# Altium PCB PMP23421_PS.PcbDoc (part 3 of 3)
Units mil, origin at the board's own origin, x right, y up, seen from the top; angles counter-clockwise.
Board outline 1978.53 x 2528.22 mil, 6 copper layers (Top Layer, Signal Layer 1, Signal Layer 2, Signal Layer 3, Signal Layer 4, Bottom Layer), stack 61.3 mil thick; 156 components, 45 nets, 410 pads, 635 vias.
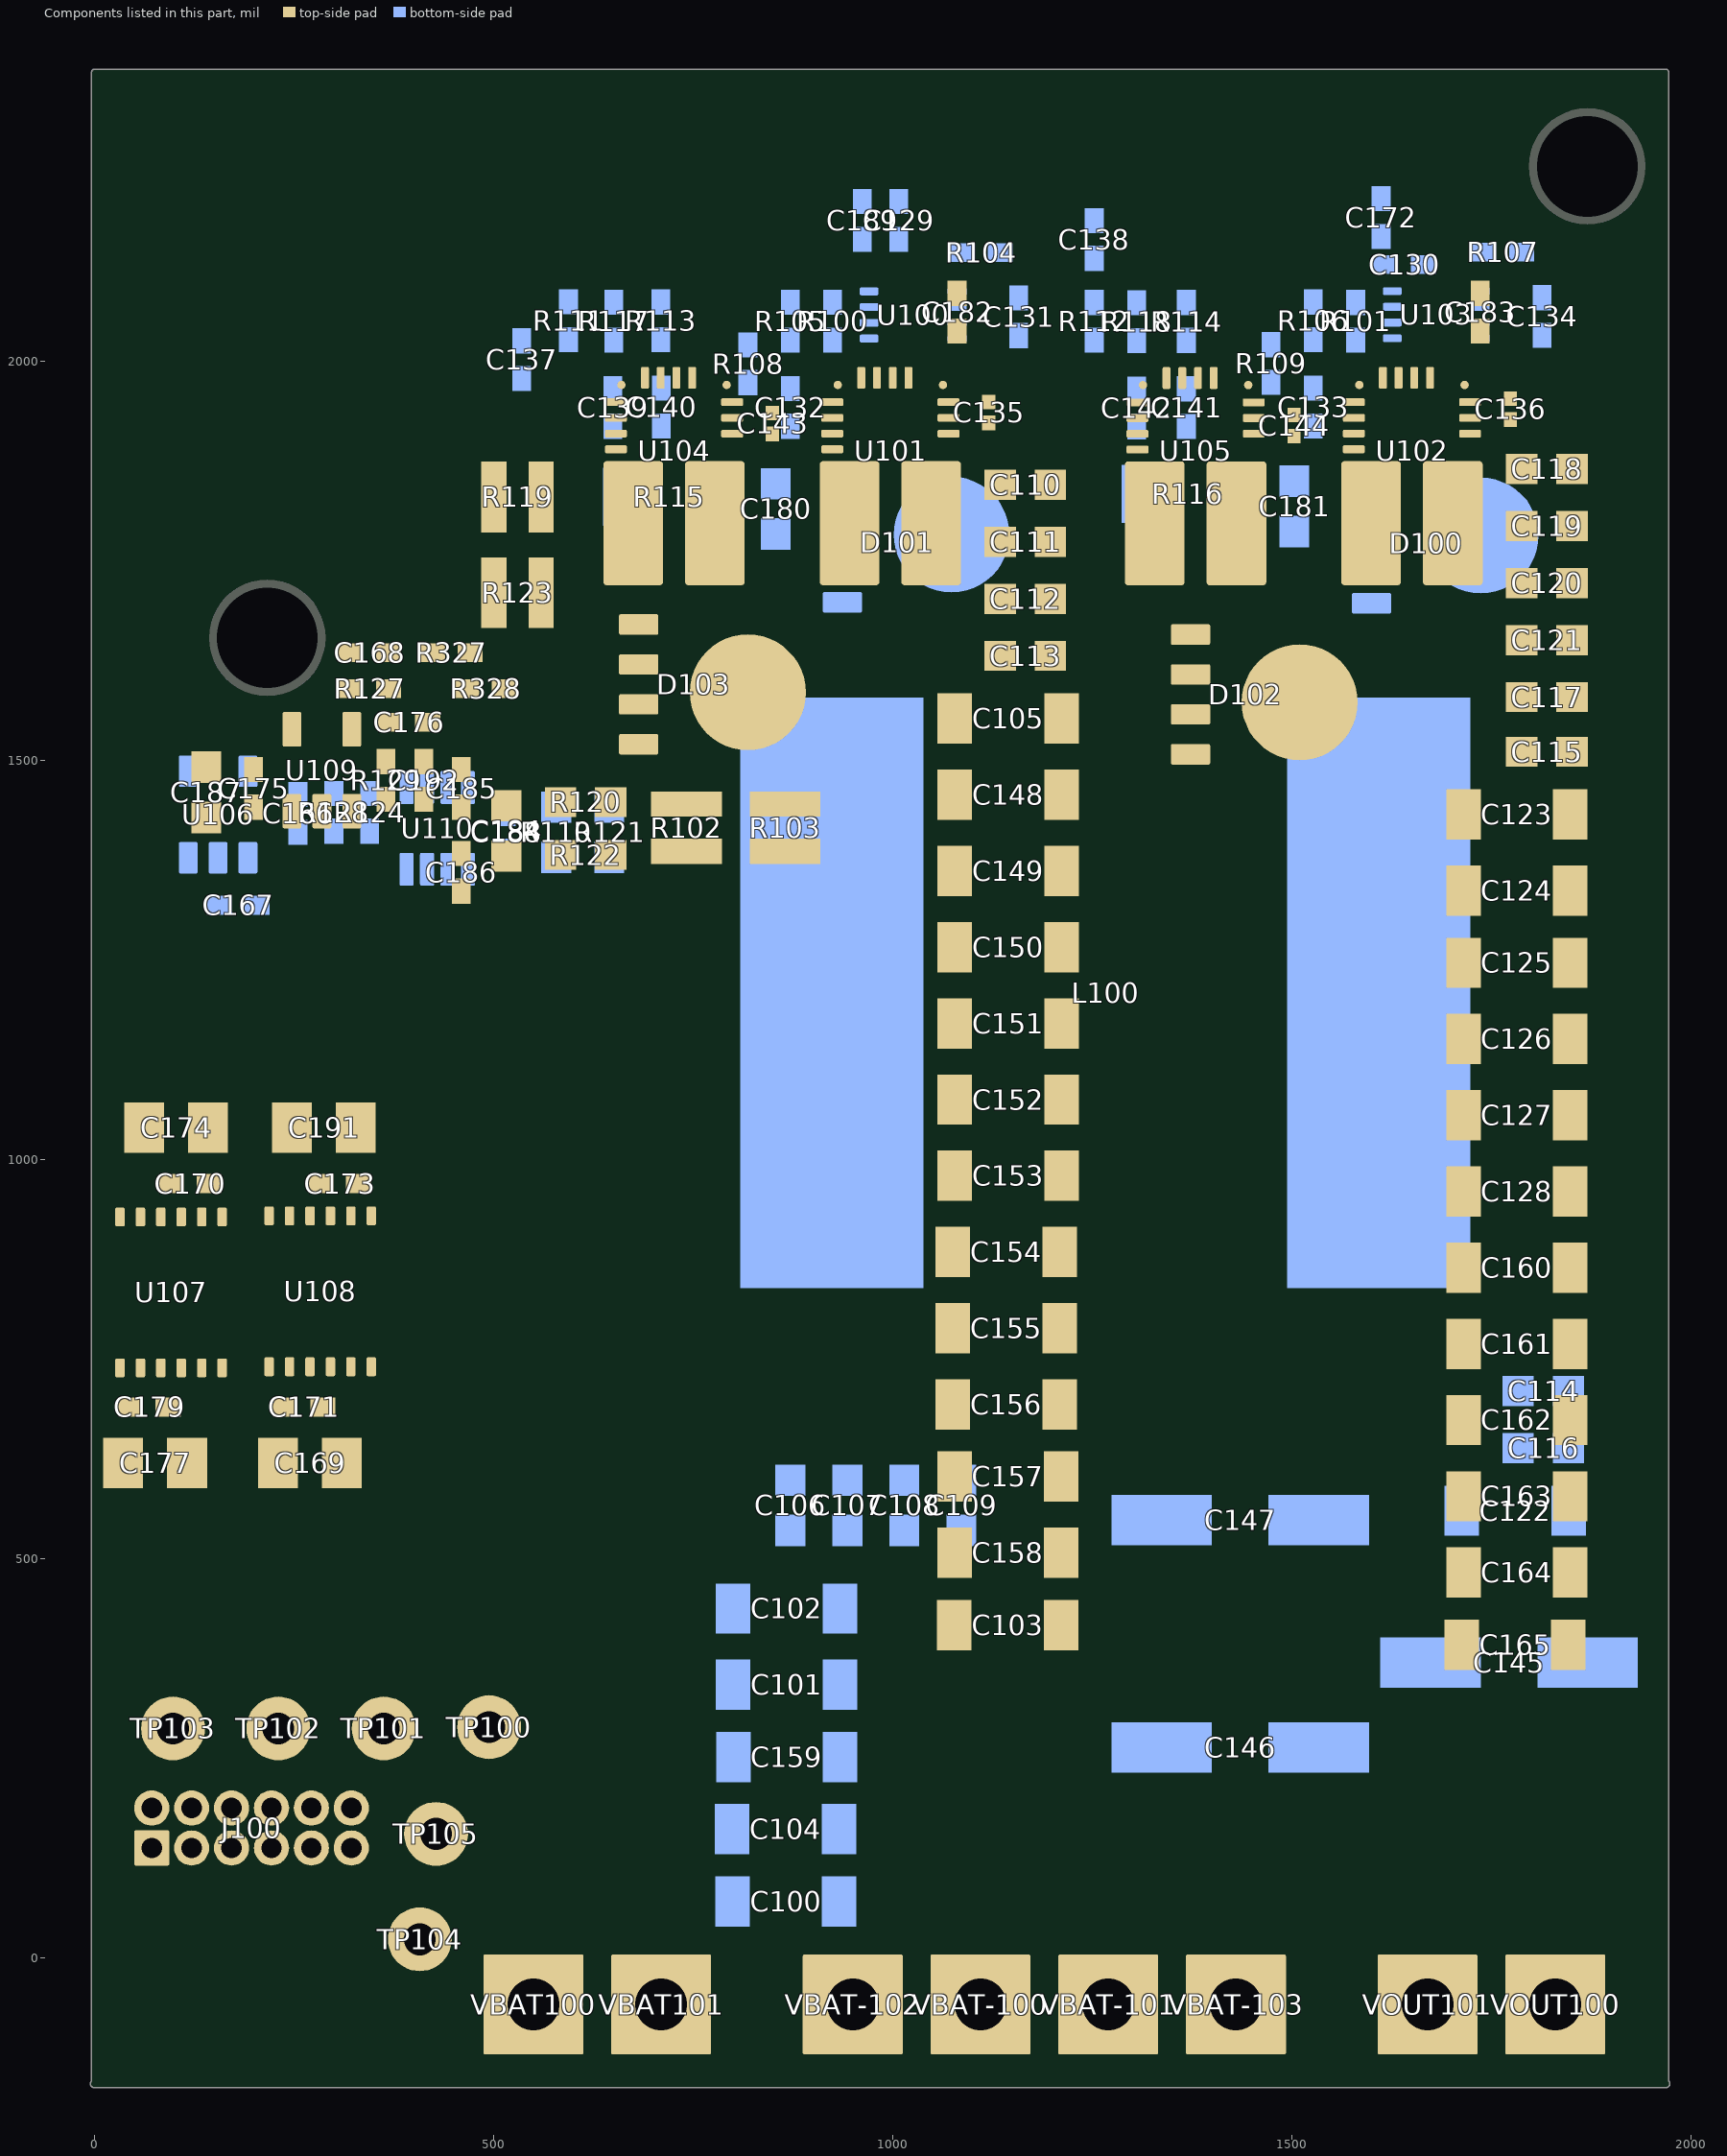
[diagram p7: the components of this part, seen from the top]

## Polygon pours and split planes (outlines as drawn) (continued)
VBAT1 on Top Layer "VBAT1" (solid, remove dead copper, pour order 86): 770,521 480,231 480,-126 496,-142 798,-142 820,-120 820,108.51 1159,447.51 1159,1607 1159,1862.53 1170,1873.53 1170,1895 1165,1900 1120.06,1900 1094.38,1874.31 1019.76,1874 1010,1864.24 1010,1726 953,1669 953,1498 935,1480 935,1234 863,1162 863,835 770,742.01
CSB on Top Layer "CSB" (solid, remove dead copper, pour order 80): 694.78,1405 681.83,1392.05 681.83,1333.27 790.1,1225 914.42,1225 924.42,1235 924.42,1389.1 908.52,1405
CSA on Top Layer "CSA" (solid, remove dead copper, pour order 76): 984.25,1905.68 975,1914.93 744.93,1914.93 740,1910 740.16,1909.84 740.16,1874.02 740.16,1535 740.67,1530.67 685,1475 685,1440 695,1430 908.52,1430 925.77,1447.25 925.77,1484.82 940.94,1500 940.94,1677.17 984.25,1720.47
48VOUT1 on Top Layer "48Vout1" (solid, remove dead copper, pour order 74): 1730.83,1885.83 1755,1910 1810,1910 1815,1905 1814.96,354.33 1964.57,204.72 1964.57,-137.8 1952.76,-149.61 1614.17,-149.61 1602.36,-137.8 1602.36,59.06 1515.75,145.67 1515.75,1274.89 1618.11,1377.25 1618.11,1662.92 1657.48,1702.29 1657.48,1877.95 1665.35,1885.83
SW2 on Top Layer "SW2" (solid, remove dead copper, pour order 72): 1393.7,1908.7 1400,1915 1625,1915 1635,1905 1635,1694.06 1610.24,1669.29 1610.24,1389.76 1599.41,1378.94 1507.87,1378.94 1429.13,1457.68 1429.13,1685.04 1393.7,1720.47
SGND on Top Layer "SGND" (solid, remove dead copper, pour order 98): 540,1882.07 547.38,1889.45 605,1889.45 605,1934.28 605.72,1935 696.29,1935 716,1915.29 715.74,1870.08 715.74,1516.67 703.76,1504.68 641.24,1504.68 540,1605.92
VBAT- on Top Layer "VBAT-" (solid, remove dead copper, pour order 136): 510,1890 425,1890 420,1885 420,1675 435,1660 510,1660 515,1665 515,1885
VBAT- on Top Layer "VBAT-" (solid, remove dead copper, pour order 138): 1270,1665.5 1300,1635.5 1300,210 1190,100 1190,-119.72 1164.72,-145 890,-145 865.21,-120 865.21,140.21 1165,440 1165,1857.44 1183.02,1875.46 1254.6,1875.46 1270,1860.06
SGND on Top Layer "SGND" (solid, remove dead copper, pour order 140): 1290,1875 1275.01,1875 1275.01,1860 1275.01,175.01 1205,105 1205,-120 1230,-145 1510,-145 1535,-120 1535,114.09 1509.78,139.31 1509.78,1363.15 1420.12,1452.81 1420.12,1684.88 1385,1720 1385,1859.4 1369.4,1875
SGND on Top Layer "SGND" (solid, remove dead copper, pour order 144): 355,750.09 355,709.75 349.84,704.59 319.45,704.89 314.57,700 314.57,690 315.39,690 320.39,685 363.87,685 372.22,676.65 372.22,675 375.3,675 377.95,677.65 374.92,680.69 374.92,765.1 375.03,1124.97 372.92,1127.08 204.36,1127.07 85,1246.44 85,1840.5 565,2320.5 1230,2320.5 1265,2355.5 1935,2355.5 1960,2330.5 1960,2020.5 1939.42,1999.92 1705.58,1999.92 1695,2010.5 1695,2165.81 1605.31,2255.5 1367.11,2255.5 1344.8,2233.19 1344.8,2140.54 1385,2100.35 1385,1913.45 1367.04,1895.5 1178.55,1895.5 1170,1904.05 1170,1928.3 1097.8,2000.5 1040,2000.5 1030,2010.49 1030,2210.49 1000,2240.5 714.09,2240.5 699.09,2225.5 699.09,2129.39 694.78,2125.08 694.78,2021.98 566.58,1893.78 421.14,1893.78 415,1887.64 415,1608.35 455,1568.35 541.65,1568.35 590,1520 590,1315.47 558.63,1284.1 558.63,482.63 470.75,394.75 470.75,-125 450.75,-145 30,-145 10,-125 10,744.05 16.04,750.09 165,750.09 165,709.85 160.11,704.95 130.85,704.95 125.35,699.44 125.35,690.17 130.51,685 190,685 195,680 234.87,680 264.52,709.66 264.52,745.9 268.71,750.09
5V on Top Layer "5V" (solid, remove dead copper, pour order 178): 20.49,750 5,734.51 5,453.42 20.31,438.12 64.46,481.95 64.46,745.54 60,750
5V on Top Layer "5V" (solid, remove dead copper, pour order 82): 205.04,750 205.04,558.4 213.57,549.87 249.36,549.87 254.5,555 254.5,745.54 250.04,750
SW2 on Top Layer "SW2" (solid, remove dead copper, pour order 180): 60,980 65,975 65,965.19 60,960.19 60,960 30,960 20,950 20,920 25,915 110,915 115.1,920.1 115.1,991.56 95,1011.65 95,1090 90,1095 30,1095 20,1085 20,990 30,980
VDD_2H_D on Top Layer "VDD_2H_D" (solid, remove dead copper, pour order 150): 115,1095 110,1090 110,1015 125,1000 125,920 130,915 170,915 170,915.1 175,920.1 175,1090 170,1095
CSA on Signal Layer 1 "CSA" (solid, remove dead copper, pour order 114): 1025,2090 1040,2075 1040,2045 1025,2030 1025,1940 980,1895 810,1895 775,1930 775,2065 775,2200 790,2215 1000,2215 1025,2190
VBAT1 on Signal Layer 1 "VBAT1" (solid, remove dead copper, pour order 128): 820,-120 795,-145 500,-145 475,-120 475,196.84 555,276.84 555,415 730,590 730,740 755,765 755.26,764.74 922.18,764.74 946.31,740.61 946.31,647.53 923.79,625 923.79,488.79 870,435 870,34.37 820,-15.63
VBAT- on Signal Layer 1 "VBAT-" (solid, remove dead copper, pour order 142): 435,1890 420,1875 420,1600 440,1580 565,1580 779.89,1365.11 922.47,1365.11 935.68,1351.89 935.68,774.32 955,755 955,643.42 935,623.42 935,485 878.58,428.58 878.58,-130.68 890,-142.1 1167.9,-142.1 1190,-120 1190,100 1300,210 1300,1635 1270,1665 1270,1860 1240,1890
SGND on Signal Layer 1 "SGND" (solid, remove dead copper, pour order 146): 694.78,2125.08 694.78,2021.98 566.58,1893.78 421.14,1893.78 415,1887.64 415,1608.35 455,1568.35 541.65,1568.35 590,1520 590,1315.47 558.63,1284.1 558.63,482.63 470.75,394.75 470.75,-125 450.75,-145 30,-145 10,-125 10,735.47 24.53,750 359.82,750 375,765.18 375,1060 307.92,1127.08 204.36,1127.07 85,1246.44 85,1840.5 565,2320.5 1230,2320.5 1265,2355.5 1935,2355.5 1960,2330.5 1960,2020.5 1939.42,1999.92 1705.58,1999.92 1695,2010.5 1695,2165.81 1605.31,2255.5 1367.11,2255.5 1344.8,2233.19 1344.8,2140.54 1385,2100.35 1385,1913.45 1367.04,1895.5 1178.55,1895.5 1170,1904.05 1170,1928.3 1097.8,2000.5 1040,2000.5 1030,2010.49 1030,2210.49 1000,2240.5 714.09,2240.5 699.09,2225.5 699.09,2129.39
SW2 on Signal Layer 1 "SW2" (solid, remove dead copper, pour order 156): 1425,2200 1445,2220 1625,2220 1690,2155 1690,1914.91 1670.09,1895 1445,1895 1425,1915
SGND on Signal Layer 1 "SGND" (solid, remove dead copper, pour order 160): 1280,1860.3 1310,1890 1945,1890 1955,1880 1955,365 1535,-55 1535,-120 1510,-145 1230,-145 1205,-120 1205,100 1310,205 1310,1640 1280,1670
SW2 on Signal Layer 1 "SW2" (solid, remove dead copper, pour order 184): 25,915 20,920 20,1085 30,1095 90,1095 95,1090 95,1075 100,1070 165,1070 175.19,1059.81 174.97,919.97 170,915
CSA on Signal Layer 1 "CSA" (solid, remove dead copper, pour order 190): 215,914.5 210,919.5 210,1084.5 220,1094.5 280,1094.5 285,1089.5 285,1074.5 290,1069.5 355,1069.5 365.19,1059.31 364.97,919.47 360,914.5
VBAT- on Signal Layer 2 "VBAT-" (solid, remove dead copper, pour order 202): 435.11,1890 420.11,1875 420.11,1600 440.11,1580 565.11,1580 780,1365.11 922.57,1365.11 935.79,1351.89 935.79,774.32 955.11,755 955.11,643.42 935.11,623.42 935.11,485 878.68,428.58 878.68,-130.68 890.11,-142.1 1168,-142.1 1190.11,-120 1190.11,100 1300.11,210 1300.11,1635 1270.11,1665 1270.11,1860 1240.11,1890
SGND on Signal Layer 2 "SGND" (solid, remove dead copper, pour order 200): 1285.18,1865.43 546.1,1865.43 540,1859.33 540,1745.67 545.67,1740 1146.91,1740 1175.94,1769.02 1256.15,1769.02 1280,1745 1280,1670 1310,1640 1310,205 1205,100 1205,-120 1230,-145 1510,-145 1535,-120 1535,-55 1955,365 1955,1880 1945,1890 1310,1890
SGND on Signal Layer 2 "SGND" (solid, remove dead copper, pour order 132): 1230,2320 1265,2355 1935,2355 1960,2330 1960,2020 1939.42,1999.42 1705.58,1999.42 1695,2010 1695,2165.31 1605.31,2255 1367.11,2255 1344.8,2232.7 1344.8,2140.04 1385,2099.85 1385,1912.96 1367.04,1895 1178.55,1895 1170,1903.55 1170,1927.8 1097.8,2000 1040,2000 1030,2010 1030,2210 1000,2240 714.09,2240 699.09,2225 699.09,2128.89 694.8,2124.6 445,2124.6 445,2200 565,2320
CSA on Signal Layer 2 "CSA" (solid, remove dead copper, pour order 108): 1025,2090 1040,2075 1040,2045 1025,2030 1025,1940 980,1895 810,1895 775,1930 775,2065 775,2198.84 791.16,2215 1000,2215 1025,2190
SGND on Signal Layer 2 "SGND" (solid, remove dead copper, pour order 148): 694.78,2125.08 694.78,2021.98 566.58,1893.78 421.14,1893.78 415,1887.64 415,1608.35 455,1568.35 541.65,1568.35 630,1480 630,155 470.75,-4.25 470.75,-125 450.75,-145 30,-145 10,-125 10,739.05 20.95,750 359.82,750 375,765.18 375,1050 297.92,1127.08 204.36,1127.07 85,1246.44 85,1840.5 565,2320.5 1230,2320.5 1265,2355.5 1935,2355.5 1960,2330.5 1960,2020.5 1939.42,1999.92 1705.58,1999.92 1695,2010.5 1695,2165.81 1605.31,2255.5 1367.11,2255.5 1344.8,2233.19 1344.8,2140.54 1385,2100.35 1385,1913.45 1367.04,1895.5 1178.55,1895.5 1170,1904.05 1170,1928.3 1097.8,2000.5 1040,2000.5 1030,2010.49 1030,2210.49 1000,2240.5 714.09,2240.5 699.09,2225.5 699.09,2129.39
SW2 on Signal Layer 2 "SW2" (solid, remove dead copper, pour order 158): 1425,2200 1445,2220 1625,2220 1690,2155 1690,1914.91 1670.09,1895 1445,1895 1425,1915
VBAT1 on Signal Layer 2 "VBAT1" (solid, remove dead copper, pour order 166): 820,-120 795,-145 500,-145 475,-120 475,-12.8 640,152.2 640,500 730,590 730,740 755,765 922.18,764.74 946.31,740.61 946.31,647.53 923.79,625 923.79,488.79 870,435 870,34.37 820,-15.63
SW2 on Signal Layer 2 "SW2" (solid, remove dead copper, pour order 188): 25,915 20,920 20,1085 30,1095 90,1095 95,1090 95,1075 100,1070 165,1070 175.19,1059.81 174.97,919.97 170,915
CSA on Signal Layer 2 "CSA" (solid, remove dead copper, pour order 194): 215,914.39 210,919.39 210,1084.39 220,1094.39 280,1094.39 285,1089.39 285,1074.39 290,1069.39 355,1069.39 365.19,1059.21 364.97,919.36 360,914.39
SW2 on Signal Layer 3 "SW2" (solid, remove dead copper, pour order 236): 1425,2200 1445,2220 1625,2220 1690,2155 1690,1914.91 1670.09,1895 1445,1895 1425,1915
CSA on Signal Layer 3 "CSA" (solid, remove dead copper, pour order 232): 1025,2090 1040,2075 1040,2045 1025,2030 1025,1940 980,1895 810,1895 775,1930 775,2065 775,2198.84 791.16,2215 1000,2215 1025,2190
CSA on Signal Layer 3 "CSA" (solid, remove dead copper, pour order 228): 215.29,914.39 210.29,919.39 210.29,1084.39 220.29,1094.39 280.29,1094.39 285.29,1089.39 285.29,1074.39 290.29,1069.39 355.29,1069.39 365.48,1059.21 365.26,919.36 360.29,914.39
SW2 on Signal Layer 3 "SW2" (solid, remove dead copper, pour order 224): 25,915 20,920 20,1085 30,1095 90,1095 95,1090 95,1075 100,1070 165,1070 175.19,1059.81 174.97,919.97 170,915
SGND on Signal Layer 3 "SGND" (solid, remove dead copper, pour order 220): 694.78,2125.08 694.78,2021.98 566.58,1893.78 421.14,1893.78 415,1887.64 415,1608.35 455,1568.35 541.65,1568.35 630,1480 630,155 470.75,-4.25 470.75,-125 450.75,-145 30,-145 10,-125 10,739.05 20.95,750 359.82,750 375,765.18 375,1050 297.92,1127.08 204.36,1127.07 85,1246.44 85,1840.5 565,2320.5 1230,2320.5 1265,2355.5 1935,2355.5 1960,2330.5 1960,2020.5 1939.42,1999.92 1705.58,1999.92 1695,2010.5 1695,2165.81 1605.31,2255.5 1367.11,2255.5 1344.8,2233.19 1344.8,2140.54 1385,2100.35 1385,1913.45 1367.04,1895.5 1178.55,1895.5 1170,1904.05 1170,1928.3 1097.8,2000.5 1040,2000.5 1030,2010.49 1030,2210.49 1000,2240.5 714.09,2240.5 699.09,2225.5 699.09,2129.39
VBAT1 on Signal Layer 3 "VBAT1" (solid, remove dead copper, pour order 208): 819.86,-120 794.86,-145 499.86,-145 474.86,-120 474.86,-12.8 639.86,152.2 639.86,500 729.86,590 729.86,740 754.86,765 922.04,764.74 946.18,740.61 946.18,647.53 923.65,625 923.65,488.79 869.86,435 869.86,34.37 819.86,-15.63
VBAT- on Signal Layer 3 "VBAT-" (solid, remove dead copper, pour order 204): 435.11,1890 420.11,1875 420.11,1600 440.11,1580 565.11,1580 780,1365.11 922.57,1365.11 935.79,1351.89 935.79,774.32 955.11,755 955.11,643.42 935.11,623.42 935.11,485 878.68,428.58 878.68,-130.68 890.11,-142.1 1168,-142.1 1190.11,-120 1190.11,100 1300.11,210 1300.11,1635 1270.11,1665 1270.11,1860 1240.11,1890
SGND on Signal Layer 3 "SGND" (solid, remove dead copper, pour order 198): 1285.18,1865.43 546.1,1865.43 540,1859.33 540,1745.67 545.67,1740 1146.91,1740 1175.94,1769.02 1256.15,1769.02 1280,1745 1280,1670 1310,1640 1310,205 1205,100 1205,-120 1230,-145 1510,-145 1535,-120 1535,-55 1955,365 1955,1880 1945,1890 1310,1890
SW2 on Signal Layer 4 "SW2" (solid, remove dead copper, pour order 234): 1425,2200 1445,2220 1625,2220 1690,2155 1690,1914.91 1670.09,1895 1445,1895 1425,1915
CSA on Signal Layer 4 "CSA" (solid, remove dead copper, pour order 230): 1025,2090 1040,2075 1040,2045 1025,2030 1025,1940 980,1895 810,1895 775,1930 775,2065 775,2198.84 791.16,2215 1000,2215 1025,2190
CSA on Signal Layer 4 "CSA" (solid, remove dead copper, pour order 226): 215.29,914.39 210.29,919.39 210.29,1084.39 220.29,1094.39 280.29,1094.39 285.29,1089.39 285.29,1074.39 290.29,1069.39 355.29,1069.39 365.48,1059.21 365.26,919.36 360.29,914.39
SW2 on Signal Layer 4 "SW2" (solid, remove dead copper, pour order 222): 25,915 20,920 20,1085 30,1095 90,1095 95,1090 95,1075 100,1070 165,1070 175.19,1059.81 174.97,919.97 170,915
SGND on Signal Layer 4 "SGND" (solid, remove dead copper, pour order 218): 694.78,2125.08 694.78,2021.98 566.58,1893.78 421.14,1893.78 415,1887.64 415,1608.35 455,1568.35 541.65,1568.35 630,1480 630,155 470.75,-4.25 470.75,-125 450.75,-145 30,-145 10,-125 10,739.05 20.95,750 359.82,750 375,765.18 375,1050 297.92,1127.08 204.36,1127.07 85,1246.44 85,1840.5 565,2320.5 1230,2320.5 1265,2355.5 1935,2355.5 1960,2330.5 1960,2020.5 1939.42,1999.92 1705.58,1999.92 1695,2010.5 1695,2165.81 1605.31,2255.5 1367.11,2255.5 1344.8,2233.19 1344.8,2140.54 1385,2100.35 1385,1913.45 1367.04,1895.5 1178.55,1895.5 1170,1904.05 1170,1928.3 1097.8,2000.5 1040,2000.5 1030,2010.49 1030,2210.49 1000,2240.5 714.09,2240.5 699.09,2225.5 699.09,2129.39
SGND on Signal Layer 4 "SGND" (solid, remove dead copper, pour order 216): 1279.86,1860.3 1309.86,1890 1944.86,1890 1954.86,1880 1954.86,365 1534.86,-55 1534.86,-120 1509.86,-145 1229.86,-145 1204.86,-120 1204.86,100 1309.86,205 1309.86,1640 1279.86,1670
VBAT- on Signal Layer 4 "VBAT-" (solid, remove dead copper, pour order 212): 433.14,1890.88 418.14,1875.88 418.14,1600.88 438.14,1580.88 563.14,1580.88 778.03,1365.98 920.6,1365.98 933.82,1352.77 933.82,775.2 953.14,755.88 953.14,644.3 933.14,624.3 933.14,485.88 876.71,429.46 876.71,-129.8 888.14,-141.22 1166.03,-141.22 1188.14,-119.12 1188.14,100.88 1298.14,210.88 1298.14,1635.88 1268.14,1665.88 1268.14,1860.88 1238.14,1890.88
48VOUT1 on Signal Layer 4 "48Vout1" (solid, remove dead copper, pour order 210): 1660,1873.15 1640,1853.15 1640,1709.42 1639.42,1709.42 1615,1685 1615,1375 1604.88,1364.88 1604.88,-136.73 1615,-146.85 1950,-146.85 1960,-136.85 1960,1766.52 1853.36,1873.15
VBAT1 on Signal Layer 4 "VBAT1" (solid, remove dead copper, pour order 206): 819.86,-120 794.86,-145 499.86,-145 474.86,-120 474.86,-12.8 639.86,152.2 639.86,500 729.86,590 729.86,740 754.86,765 922.04,764.74 946.18,740.61 946.18,647.53 923.65,625 923.65,488.79 869.86,435 869.86,34.37 819.86,-15.63

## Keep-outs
Keep-Out Layer:
  text ".Layer_Name" at 577,-858.49 h60

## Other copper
Top Layer:
  text ".Layer_Name" at 577,-858.49 h60
Bottom Layer:
  text ".Layer_Name" at 577,-858.49 h60

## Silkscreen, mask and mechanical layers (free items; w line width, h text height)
Top Overlay:
  lines w10: 20,955 20,965 10,975 10,1105 20,1115 20,1140 ; 665,1239.83 665,1240.1 708.24,1283.34 708.24,1325 ; 775.35,900 766.48,900 716.48,850 569.46,850 419.46,1000 419.46,1110.54 367.34,1162.66 367.34,1285 380.8,1285 619.83,1285 697,1207.83 697,1104.07 746.07,1055 893.39,1055 901.21,1047.18
  text "PMP23421 Power Stage RevC" at 80,1375 h72.83 r90
  text "VBat+" at 560,50 h72.83
  text "VBus-" at 1260,50 h72.83
  text "VBus+" at 1670,50 h72.83
  text "VBat-" at 940,45 h72.83
  text ".Layer_Name" at 577,-858.49 h60
Bottom Overlay:
  lines w10: 330,-10 354.33,-10 ; 362.45,342.17 362.45,384.49 377.95,400 389.79,400 404.79,415 404.79,432.2 ; 375,120 330,75 330,-45 380,-95 ; 495,2097.62 546.92,2097.62 ; 1178.54,2129.69 1179.06,2129.17 ; 1198.87,2091.46 1198.87,2048.33 1211.44,2035.76 1220,2035.76 ; 1600,1975 1635.34,1975 1674.18,1936.16 1830,1936.16 ; 1663.79,2155 1663.79,2228.79 1675,2240 1716.44,2240 ; 1830.77,1899.18 1830.77,1989.61 1841.07,1999.92 1925,1999.92 1925.72,1999.92 1935,1990.63 1935,1905.68 1935,1896.35 ; 121.63,1900 121.63,2186.63 495,2188.98 494.46,2188.43 494.46,1905 489.46,1900 121.63,1900
  text "Bus_H" at 500.4,455 h60
  text "Bat_H" at 157.03,370 h60
  text "Bat_L" at 310.45,370 h60
  text "Bus_L" at 602.03,363.24 h60
  text "GND" at 428.85,-40 h60 r90
  text ".Layer_Name" at 577,-858.49 h60
Top Paste:
  text ".Layer_Name" at 577,-858.49 h60
Bottom Paste:
  rectangle: 1740.82,765 1855,1650
  rectangle: 620,40 760,760
  rectangle: 1690,15 1930,161.28
  text ".Layer_Name" at 577,-858.49 h60
Top Solder:
  rectangle: 1235,1595 1312.72,1690
  rectangle: 1480,1725 1550,1871.38
  rectangle: 825.15,1723.35 900,1872.96
  rectangle: 501.39,1570.23 565,1789.78
  rectangle: 959.22,1225 1077.37,1665
  rectangle: 909.14,935 1077.37,1165
  rectangle: 780,360 1030,910
  rectangle: 1631.39,1490 1750,1665
  rectangle: 1530,355 1670,1266.06
  rectangle: 1535,110 1945,325
  text ".Layer_Name" at 577,-858.49 h60
  text ".Layer_Name" at 577,-858.49 h60
Bottom Solder:
  text ".Layer_Name" at 577,-858.49 h60
Drill Guide:
  text ".Layer_Name" at 577,-858.49 h60
M1 Board Outline:
  lines w7.01: 0,-157.48 0,1968.5 ; 0,0 0,2362.2 1968.5,2362.2 1968.5,-157.48
  lines w10: 0,-157.48 1968.5,-157.48
  text ".Layer_Name" at 577,-858.49 h60
M2 Board Dimensions:
  rectangle: 125,-400 500,-275
  rectangle: 0,-275 125,-150
  lines w7: 0,-275 1000,-275 ; 125,-400 125,-150 ; 250,-400 250,-150 ; 500,-400 500,-150 ; 750,-400 750,-150 ; 0,-400 0,-150 1000,-150 1000,-400 0,-400
  text ".Layer_Name" at 577,-858.49 h60
M3 3D STEP Top:
  text ".Layer_Name" at 577,-858.49 h60
M4 3D STEP Bottom:
  text ".Layer_Name" at 577,-858.49 h60
M5 Assembly Top:
  lines w10: -292,-930.17 6308,-930.17 ; -292,-726.83 6310,-726.83 ; -292,-523.5 -292,-1133.5 3713,-1133.5 6310,-1133.5 6310,-523.5 -291.5,-523.5 -291.5,-1133.5 1284,-1133.5 ; 2173,-1133.5 2173,-523.5 ; 3440,-726.83 3440,-523.5 ; 4280,-726.83 4280,-523.5 ; 4902,-1140 4902,-937.17
  text "COMPONENTS MARKED 'DNP' SHOULD NOT BE POPULATED." at 1153.5,-318.5 h60
  text "ASSEMBLY VARIANT:" at 1153,-434 h60
  text ".VariantName" at 2189,-434 h60
  text "PCB VIEWED FROM TOP SIDE" at -228.5,-655.67 h60
  text "BOARD #:" at 2248,-655.67 h60
  text ".PRJ_Number" at 2793.5,-655.67 h60
  text "REV:" at 3638,-655.67 h60
  text ".PCB_Rev" at 3929.5,-655.67 h60
  text "SVN REV:" at 4476,-655.67 h60
  text ".VersionControl_RevNumber" at 4982,-655.67 h60
  text "TID #:" at 2248,-859 h60
  text ".TID" at 2793.5,-859 h60
  text "PLOT NAME =" at -228.5,-1064.34 h60
  text ".plot_File_Name" at 577,-1064.34 h60
  text "GENERATED    :" at 2250,-1064.34 h60
  text ".Print_Date" at 3119.5,-1064.34 h60
  text ".Print_Time" at 3848.5,-1064.34 h60
  text "TEXAS INSTRUMENTS" at 5113,-1064.34 h60
M6 Assembly Bottom:
  lines w10: -292.5,-727.33 6309.5,-727.33 ; -290.5,-930.67 6309.5,-930.67 ; 1115.5,-1140.5 1115.5,-937.67 ; 1737.5,-727.33 1737.5,-524 ; 2577.5,-727.33 2577.5,-524 ; 3844.5,-1134 3844.5,-524 ; 4733.5,-1134 6309,-1134 6309,-524 -292.5,-524 -292.5,-1134 2304.5,-1134 6309.5,-1134 6309.5,-524
  text "COMPONENTS MARKED 'DNP' SHOULD NOT BE POPULATED." at 6102,-318 h60
  text ".VariantName" at 5058,-434 h60
  text "ASSEMBLY VARIANT:" at 6097,-434 h60
  text ".VersionControl_RevNumber" at 1035.5,-656.17 h60
  text "SVN REV:" at 1541.5,-656.17 h60
  text ".PCB_Rev" at 2088,-656.17 h60
  text "REV:" at 2379.5,-656.17 h60
  text ".PRJ_Number" at 3224,-656.17 h60
  text "BOARD #:" at 3769.5,-656.17 h60
  text "PCB VIEWED FROM BOTTOM SIDE" at 6246,-656.17 h60
  text ".TID" at 3224,-859.5 h60
  text "TID #:" at 3769.5,-859.5 h60
  text "TEXAS INSTRUMENTS" at 904.5,-1064.84 h60
  text ".Print_Time" at 2169,-1064.84 h60
  text ".Print_Date" at 2898,-1064.84 h60
  text "GENERATED    :" at 3767.5,-1064.84 h60
  text ".plot_File_Name" at 5440.5,-1064.84 h60
  text "PLOT NAME =" at 6246,-1064.84 h60
M9 Title Sheet:
  drawing of 57 lines, arcs and shapes, not listed
  text "1" at 739.84,8036.5 h70
  text "2" at 3235.5,8036.5 h70
  text "3" at 5724.84,8036.5 h70
  text "4" at 8231.51,8036.5 h70
  text "5" at 10730.5,8036.5 h70
  text "6" at 13235.5,8036.5 h70
  text "A" at -416.5,6893.5 h70
  text "A" at 14383.5,6893.5 h70
  text "B" at -416.5,4513.5 h70
  text "B" at 14383.5,4513.5 h70
  text "C" at -416.5,2138.5 h70
  text "C" at 14383.5,2138.5 h70
  text "PROJECT TITLE:" at 11343.5,277.5 h45
  text ".PRJ_Title" at 11393.5,144.17 h70
  text "DESIGNED FOR:" at 11343.5,-23.5 h45
  text ".PRJ_Customer" at 11393.5,-163.5 h70
  text "D" at -416.5,-231.5 h70
  text "D" at 14383.5,-231.5 h70
  text "FILE NAME:" at 11343.5,-323.5 h45
  text ".PCB_File_Name_No_Path" at 11393.5,-443.5 h70
  text "Texas Instruments (TI) and/or its licensors do not warrant the accuracy or completeness of this specification" at 6374,-605.34 h45
  text "ENGINEER:" at 11343.5,-613.5 h45
  text "LAYOUT BY:" at 12848.5,-613.5 h45
  text "or any information contained therein. TI and/or its licensors do not warrant that this design will meet" at 6329.01,-718 h45
  text ".PRJ_Engineer" at 11393.5,-768.49 h70
  text ".PCB_Layout" at 12899,-768.49 h70
  text "the specifications, will be suitable for your application or fit for any particular purpose, or will operate in" at 6329.01,-830.67 h45
  text ".Layer_Name" at 577,-858.49 h60
  text "ALTIUM DESIGNER VERSION:" at 12848.5,-923.5 h45
  text "an implementation. TI and/or its licensors do not warrant that the design is production worthy. You should" at 6329.01,-943.33 h45
  text "completely validate and test your design implementation to confirm the system functionality for your application." at 6374,-1056 h45
  text ".print_Scale" at 11393.5,-1056.83 h70
  text ".Application_BuildNumber" at 12899,-1056.83 h70
  text "1" at 739.84,-1263.5 h70
  text "2" at 3235.5,-1263.5 h70
  text "3" at 5724.84,-1263.5 h70
  text "4" at 8231.51,-1263.5 h70
  text "5" at 10730.5,-1263.5 h70
  text "6" at 13235.5,-1263.5 h70
M10 Fab Notes:
  drawing of 189 lines, arcs and shapes, not listed
  text "DESIGN INFORMATION" at 12382.02,6356.17 h60
  text "MIN. TRACK WIDTH:" at 11737.46,6224.05 h60
  text "8" at 12833.7,6224.05 h60
  text "MIL" at 12988.46,6224.05 h60
  text "MIN. CLEARANCE:" at 11737.46,6099.92 h60
  text "0.2" at 12773.7,6099.93 h60
  text "mm" at 12988.46,6099.92 h60
  text "MIN. VIA PAD SIZE:" at 11737.46,5975.8 h60
  text "24" at 12803.71,5975.8 h60
  text "MIL" at 12988.46,5975.8 h60
  text "0.05mm (2MIL)" at 12432.46,5845.9 h60
  text "MINIMUM ANNULAR RING" at 11408.23,5837.67 h60
  text "EXTERNAL" at 13140.46,5837.67 h60
  text "PER" at 11608.23,5727.55 h60
  text "IPC-D-275 CLASS 2 LEVEL C" at 11828.23,5727.54 h60
  text "MIL, HOLES" at 13316.46,5627.07 h60
  text "+/-" at 12924,5618.48 h60
  text "+/-" at 13778,5618.48 h60
  text "REGISTRATION TOLERANCES:" at 11408.23,5617.42 h60
  text "METAL" at 12608,5617.42 h60
  text "5" at 13184.2,5617.42 h60
  text "3" at 14017.2,5617.42 h60
  text "MIL" at 14133.46,5617.42 h60
  text "HOLE SIZE TOLERANCE (UNLESS OTHERWISE SPECIFIED):" at 11408.23,5519.1 h60
  text "+/-" at 13778,5516.23 h60
  text "3" at 14017.2,5515.17 h60
  text "MIL" at 14133.46,5515.17 h60
  text "MATERIAL:" at 11333.46,5377.52 h60
  text "FR-4 High Tg" at 12319.9,5249 h60
  text "X" at 12175.46,5241.01 h60
  text "FR-408" at 11754.46,5236.49 h60
  text "OTHER" at 13242.46,5236.49 h60
  text "62 MIL (1.6mm) +/-10%" at 12074.56,5093.46 h60
  text "X" at 11954.46,5091.01 h60
  text "THICKNESS:" at 11408.23,5085.24 h60
  text "OTHER" at 13359.46,5085.24 h60
  text "TOLERANCE:" at 11408.23,4946.92 h60
  text "X" at 12256.46,4946.92 h60
  text "ANSI IPC-6012 TYPE 3 CLASS 2" at 12434.48,4946.92 h60
  text "OTHER +/-" at 12434.46,4802.73 h60
  text "BOW & TWIST:" at 11408.23,4657.54 h60
  text "X" at 12256.46,4657.54 h60
  text "ANSI IPC-6012 TYPE 3 CLASS 2" at 12434.48,4657.54 h60
  text "OTHER +/-" at 12434.46,4510.85 h60
  text "DRILLING:" at 11333.46,4380.23 h60
  text "NC_DRILL FILES" at 13094.46,4275.04 h60
  text "REFERENCE:" at 11408.23,4271.1 h60
  text "X" at 12065.46,4271.01 h60
  text "AS SHOWN" at 12243.46,4271.1 h60
  text "X" at 12966.46,4271.1 h60
  text "OTHER" at 13392.46,4128.85 h60
  text "PTH COPPER THICKNESS:" at 11407.91,4125.32 h60
  text "X" at 12547.14,4125.32 h60
  text "20-30 um" at 12675.14,4125.32 h60
  text "BOARD FINISH:" at 11333.46,3977.73 h60
  text "SILKSCREEN:" at 11488.68,3867.6 h60
  text "X" at 12446.46,3867.6 h60
  text "TOP" at 12563.46,3867.6 h60
  text "X" at 12956.46,3867.6 h60
  text "BOTTOM" at 13074.46,3867.6 h60
  text "SILKSCREEN COLOR:" at 11488.68,3712.41 h60
  text "X" at 12445.46,3712.41 h60
  text "WHITE" at 12563.46,3712.41 h60
  text "OTHER" at 13074.46,3712.41 h60
  text "X" at 12576.46,3568.96 h60
  text "GREEN" at 12694.46,3568.96 h60
  text "OTHER" at 13312.46,3568.96 h60
  text "SOLDER RESIST COLOR:" at 11488.68,3562.1 h60
  text "X" at 12576.46,3414.71 h60
  text "MATTE" at 12694.46,3414.71 h60
  text "SEMI-GLOSS" at 13312,3414.07 h60
  text "IMMERSION GOLD (ENIG)" at 12394.46,3241.94 h60
  text "ENEPIG" at 13732,3234.72 h60
  text "SURFACE FINISH:" at 11333.46,3233.72 h60
  text "X" at 12216.46,3233.72 h60
  text "IMM. TIN/SILVER OR EQUIV" at 11663,3096.4 h60
  text "OTHER" at 13094.46,3092.47 h60
  text "ARRAY/PANEL:" at 11333.46,2937.09 h60
  text "CUT AND TRIM PER M1 BOARD OUTLINE" at 12394.46,2928.87 h60
  text "N.C. ROUTE" at 12394.46,2792.9 h60
  text "X" at 13082.46,2792.9 h60
  text "V. SCORE" at 13260.46,2792.9 h60
  text "CERTIFICATION:" at 11333.46,2663.77 h60
  text "MATERIALS AND WORKMANSHIP FOR ALL PCBS" at 12058.46,2663.77 h60
  text "TO MEET OR EXCEED THE REQUIREMENTS OF:" at 12058.46,2569.71 h60
  text "X" at 11695.97,2441.08 h60
  text "ANSI IPC-A-600F CLASS ->" at 11823.96,2441.08 h60
  text "X" at 13471.97,2441.08 h60
  text "2" at 13581.96,2441.08 h60
  text "1" at 13266.96,2439.58 h60
  text "3" at 13935.96,2439.58 h60
  text "X" at 12507.97,2293.39 h60
  text "RoHS" at 12635.96,2293.39 h60
  text "OTHER" at 13280.36,2293.39 h60
  text "PER ORDER" at 13677.42,2293.39 h60
  text "ALL BOARDS MUST MEET OR EXCEED UL94-V0 REQUIREMENTS." at 11361,2139.57 h60
  text "PCB MUST BEAR THE UL94V-0 UL REGISTERED MATERIAL ID NUMBER" at 11361,2023.5 h60
  text "ADDITIONAL REQUIREMENTS:" at 11333.46,1854.08 h60
  text "MICROSECTION:" at 11408.23,1746.95 h60
  text "YES" at 12313.96,1746.95 h60
  text "REQUIRED" at 13175.46,1602.62 h60
  text "BARE BOARD ELEC. TEST:" at 11408.23,1599.76 h60
  text "NONE" at 12713.96,1599.76 h60
  text "X" at 13057.46,1599.76 h60
  text "PER ORDER" at 13767.46,1599.76 h60
  text "XX MIL VIAS REQUIRE NON-CONDUCTIVE FILL AND PLANARIZE" at 11576.38,1394.82 h59
  text "XX MIL VIAS REQUIRE CONDUCTIVE FILL AND PLANARIZE" at 11584.38,1290.84 h60
  text "OUTER XX MIL TRACES REQUIRE 50 OHM SINGLE-ENDED IMPEDANCE" at 11583.39,1127.46 h58
  text "LAYER 2 & 3 (INNER LAYERS) XX MIL WIDE, XX MIL SPACE / TRACES REQUIRE 100 OHM DIFFERENTIAL IMPEDANCE" at 11575.39,891.74 h60
  text ".Layer_Name" at 577,-858.49 h60
M11 Gerber Information:
  lines w10: -292,-930.17 6308,-930.17 ; -292,-726.83 6310,-726.83 ; -292,-523.5 -292,-1133.5 3713,-1133.5 6310,-1133.5 6310,-523.5 -291.5,-523.5 -291.5,-1133.5 1284,-1133.5 ; 2173,-1133.5 2173,-523.5 ; 3440,-726.83 3440,-523.5 ; 4280,-726.83 4280,-523.5 ; 4902,-1140 4902,-937.17
  text "ALL ARTWORK VIEWED FROM TOP SIDE" at -228.5,-655.67 h60
  text "BOARD #:" at 2248,-655.67 h60
  text ".PRJ_Number" at 2793.5,-655.67 h60
  text "REV:" at 3638,-655.67 h60
  text ".PCB_Rev" at 3929.5,-655.67 h60
  text "SVN REV:" at 4476,-655.67 h60
  text ".VersionControl_RevNumber" at 4982,-655.67 h60
  text "LAYER NAME =" at -228.5,-858.49 h60
  text "TID #:" at 2248,-859 h60
  text ".TID" at 2793.5,-859 h60
  text "PLOT NAME =" at -228.5,-1064.34 h60
  text ".plot_File_Name" at 577,-1064.34 h60
  text "GENERATED    :" at 2250,-1064.34 h60
  text ".Print_Date" at 3119.5,-1064.34 h60
  text ".Print_Time" at 3848.5,-1064.34 h60
  text "TEXAS INSTRUMENTS" at 5113,-1064.34 h60
M12 Stackup:
  drawing of 399 lines, arcs and shapes, not listed
  text "Layer" at 0.34,5870 h60
  text "Name" at 410.26,5870 h60
  text "Material" at 1350,5870 h60
  text "Thickness" at 2209.76,5870 h60
  text "Constant" at 2859.6,5870 h60
  text "Board Layer Stack" at 3429.46,5870 h60
  text "1" at 0.34,5750 h60
  text "Top Overlay" at 410.26,5750 h60
  text "2" at 0.34,5630 h60
  text "Top Solder" at 410.26,5630 h60
  text "Solder Resist" at 1350,5630 h60
  text "0.39mil" at 2209.76,5630 h60
  text "3.5" at 2859.6,5630 h60
  text "3" at 0.34,5510 h60
  text "Top Layer" at 410.26,5510 h60
  text "Copper" at 1350,5510 h60
  text "2.80mil" at 2209.76,5510 h60
  text "4" at 0.34,5390 h60
  text "Dielectric 2" at 410.26,5390 h60
  text "FR-4" at 1350,5390 h60
  text "5.50mil" at 2209.76,5390 h60
  text "4.2" at 2859.6,5390 h60
  text "5" at 0.34,5270 h60
  text "Signal Layer 1" at 410.26,5270 h60
  text "Copper" at 1350,5270 h60
  text "2.80mil" at 2209.76,5270 h60
  text "6" at 0.34,5150 h60
  text "Dielectric1" at 410.26,5150 h60
  text "FR-4" at 1350,5150 h60
  text "14.00mil" at 2209.76,5150 h60
  text "4.2" at 2859.6,5150 h60
  text "7" at 0.34,5030 h60
  text "Signal Layer 2" at 410.26,5030 h60
  text "Copper" at 1350,5030 h60
  text "2.80mil" at 2209.76,5030 h60
  text "8" at 0.34,4910 h60
  text "Dielectric 3" at 410.26,4910 h60
  text "FR-4" at 1350,4910 h60
  text "5.50mil" at 2209.76,4910 h60
  text "4.2" at 2859.6,4910 h60
  text "9" at 0.34,4790 h60
  text "Signal Layer 3" at 410.26,4790 h60
  text "Copper" at 1350,4790 h60
  text "2.80mil" at 2209.76,4790 h60
  text "10" at 0.34,4670 h60
  text "Dielectric 4" at 410.26,4670 h60
  text "FR-4" at 1350,4670 h60
  text "14.00mil" at 2209.76,4670 h60
  text "4.2" at 2859.6,4670 h60
  text "11" at 0.34,4550 h60
  text "Signal Layer 4" at 410.26,4550 h60
  text "Copper" at 1350,4550 h60
  text "2.80mil" at 2209.76,4550 h60
  text "12" at 0.34,4430 h60
  text "Dielectric 5" at 410.26,4430 h60
  text "FR-4" at 1350,4430 h60
  text "5.50mil" at 2209.76,4430 h60
  text "4.2" at 2859.6,4430 h60
  text "13" at 0.34,4310 h60
  text "Bottom Layer" at 410.26,4310 h60
  text "Copper" at 1350,4310 h60
  text "2.80mil" at 2209.76,4310 h60
  text "14" at 0.34,4190 h60
  text "Bottom Solder" at 410.26,4190 h60
  text "Solder Resist" at 1350,4190 h60
  text "0.39mil" at 2209.76,4190 h60
  text "3.5" at 2859.6,4190 h60
  text "15" at 0.34,4070 h60
  text "Bottom Overlay" at 410.26,4070 h60
  text ".Layer_Name" at 577,-858.49 h60
M13 Component Bodies Top:
  text ".Layer_Name" at 577,-858.49 h60
M14 Component Bodies Bottom:
  text ".Layer_Name" at 577,-858.49 h60
M15 Courtyards Top:
  text ".Layer_Name" at 577,-858.49 h60
M16 Courtyards Bottom:
  text ".Layer_Name" at 577,-858.49 h60
Drill Drawing:
  lines w10: -6.9,5580.78 6.91,5580.78 20.72,5566.97 34.54,5580.78 48.35,5580.78 34.54,5594.59 48.35,5608.41 34.54,5608.41 20.72,5622.22 6.91,5608.41 -6.9,5608.41 6.91,5594.59 -6.9,5580.78 ; -6.9,5691.29 20.72,5705.1 48.35,5691.29 34.54,5718.91 48.35,5746.54 20.72,5732.73 -6.9,5746.54 6.91,5718.91 -6.9,5691.29 ; -6.9,5870.86 48.35,5870.86 20.72,5815.61 -6.9,5870.86 ; -6.9,5953.74 6.91,5953.74 6.91,5939.93 34.54,5939.93 34.54,5953.74 48.35,5953.74 48.35,5981.37 34.54,5981.37 34.54,5995.18 6.91,5995.18 6.91,5981.37 -6.9,5981.37 -6.9,5953.74 ; -6.9,6064.25 48.35,6064.25 48.35,6119.5 -6.9,6119.5 -6.9,6064.25
  lines w12: -56.99,5529.67 3174.5,5529.67 ; -56.99,6151.27 3174.5,6151.27 ; 280.87,5405.35 280.87,6275.59 ; 612.87,5405.35 612.87,6275.59 ; 1249.43,5405.35 1249.43,6275.59 ; 1508.57,5405.35 1508.57,6275.59 ; 1883.73,5405.35 1883.73,6275.59 ; 2608.06,5405.35 2608.06,6275.59 ; -56.99,5405.35 3174.5,5405.35 3174.5,6275.59 -56.99,6275.59 -56.99,5405.35
  text "Symbol" at 17.6,6188.57 h72
  text "Quantity" at 318.17,6188.57 h72
  text "Finished Hole Size" at 650.17,6188.57 h72
  text "Plated" at 1286.73,6188.57 h72
  text "Hole Type" at 1545.87,6188.57 h72
  text "Drill Layer Pair" at 1921.03,6188.57 h72
  text "Hole Tolerance" at 2645.36,6188.57 h72
  text "635" at 318.17,6064.25 h60
  text "10.00mil (0.254mm)" at 650.17,6064.25 h60
  text "PTH" at 1286.73,6064.25 h60
  text "Round" at 1545.87,6064.25 h60
  text "Top Layer - Bottom Layer" at 1921.03,6064.25 h60
  text "12" at 318.17,5939.93 h60
  text "25.59mil (0.650mm)" at 650.17,5939.93 h60
  text "PTH" at 1286.73,5939.93 h60
  text "Round" at 1545.87,5939.93 h60
  text "Top Layer - Bottom Layer" at 1921.03,5939.93 h60
  text "6" at 318.17,5815.61 h60
  text "40.00mil (1.016mm)" at 650.17,5815.61 h60
  text "PTH" at 1286.73,5815.61 h60
  text "Round" at 1545.87,5815.61 h60
  text "Top Layer - Bottom Layer" at 1921.03,5815.61 h60
  text "8" at 318.17,5691.29 h60
  text "64.96mil (1.650mm)" at 650.17,5691.29 h60
  text "PTH" at 1286.73,5691.29 h60
  text "Round" at 1545.87,5691.29 h60
  text "Top Layer - Bottom Layer" at 1921.03,5691.29 h60
  text "2" at 318.17,5566.97 h60
  text "125.98mil (3.200mm)" at 650.17,5566.97 h60
  text "PTH" at 1286.73,5566.97 h60
  text "Round" at 1545.87,5566.97 h60
  text "Top Layer - Bottom Layer" at 1921.03,5566.97 h60
  text "663 Total" at 318.17,5442.65 h60
  text ".Layer_Name" at 577,-858.49 h60
M17 Embedded Cavity:
  text ".Layer_Name" at 577,-858.49 h60
M18 Embedded Assembly:
  text ".Layer_Name" at 577,-858.49 h60
M19 Embedded Keepout:
  text ".Layer_Name" at 577,-858.49 h60

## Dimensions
0,-157.48 to 0,2362.2 on M2 Board Dimensions
0,-157.48 to 1968.5,-157.48 on M2 Board Dimensions
0,-400 to 1000,-400 on M2 Board Dimensions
